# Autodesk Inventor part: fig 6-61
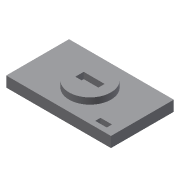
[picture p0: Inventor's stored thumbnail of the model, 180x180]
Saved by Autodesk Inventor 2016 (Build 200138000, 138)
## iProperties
Created: 2007-01
Part Number: fig 6-61
Document SubType Name: Modeling
Designer: Administrator
Density: 1 g/cm^3
Material: Generic
Appearance: Default
Author: Administrator
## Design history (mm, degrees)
sketch "Sketch1"
  geometry: L1 (-50, 30)-(50, 30); L2 (50, 30)-(50, -30); L3 (50, -30)-(-50, -30); L4 (-50, -30)-(-50, 30); 1 further point
  constraints: 8 end point, 2 parallel, 1 horizontal, 1 perpendicular, 1 other
  dimensions: "d0" = 50 distance from line of L4 point (0, 0); "d1" = 100 distance of L1.start L1.end; "d2" = 30 distance from line of L3 point (0, 0); "d3" = 60 distance between parallel lines of L3 L1
extrude "Extrusion1" new body sketch "Sketch1" distance "d4" = 10; taper "d5" = 0 deg
sketch "Sketch2"
  geometry: L1 (10, -4)-(-10, -4); L2 (-10, -4)-(-10, 4); L3 (-10, 4)-(10, 4); L4 (10, 4)-(10, -4); C1 r 20 at (0, 0); 1 further point
  constraints: 8 end point, 2 parallel, 1 centre point, 1 coincident, 1 horizontal, 1 perpendicular, 1 other
  dimensions: "d6" = 40 diameter of C1; "d7" = 4 distance from line of L3 point (0, 0); "d8" = 8 distance between parallel lines of L1 L3; "d9" = 10 distance from line of L2 point (0, 0); "d10" = 20 distance between parallel lines of L4 L2
extrude "Extrusion2" join sketch "Sketch2" distance "d11" = 6; taper "d12" = 0 deg
sketch "Sketch3"
  geometry: L1 (30, -20)-(41, -20); L2 (41, -20)-(41, -25); L3 (41, -25)-(30, -25); L4 (30, -25)-(30, -20)
  constraints: 8 end point, 2 parallel, 1 horizontal, 1 perpendicular
extrude "Extrusion3" cut sketch "Sketch3" stored distance "d13" = 10; taper "d14" = 0 deg
body "Solid1"
